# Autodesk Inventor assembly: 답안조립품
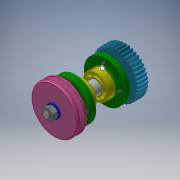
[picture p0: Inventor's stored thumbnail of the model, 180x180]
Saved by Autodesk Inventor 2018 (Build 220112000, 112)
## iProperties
Created: 2023-08
Part Number: 답안조립품
Material: 일반
Document SubType Name: Assembly
Designer: home
Author: home
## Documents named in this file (12)
- C:\Users\home\Desktop\730806V1002\답안조립품.iam
- C:\Users\home\Desktop\730806V1002\본체.ipt
- C:\Users\home\Desktop\730806V1002\V벨트풀리.ipt
- C:\Users\home\Desktop\730806V1002\너트 M12x1.25.ipt
- C:\Users\home\Desktop\730806V1002\베어링 6204.ipt
- C:\Users\home\Desktop\730806V1002\볼트 M4 x 12.ipt
- C:\Users\home\Desktop\730806V1002\스퍼기어.ipt
- C:\Users\home\Desktop\730806V1002\오일실 20x35x8.ipt
- C:\Users\home\Desktop\730806V1002\와셔 12x24.ipt
- C:\Users\home\Desktop\730806V1002\축.ipt
- C:\Users\home\Desktop\730806V1002\커버.ipt
- C:\Users\home\Desktop\730806V1002\키 5x5.ipt
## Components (1 placed, 1 different names)
1. V벨트풀리:1
